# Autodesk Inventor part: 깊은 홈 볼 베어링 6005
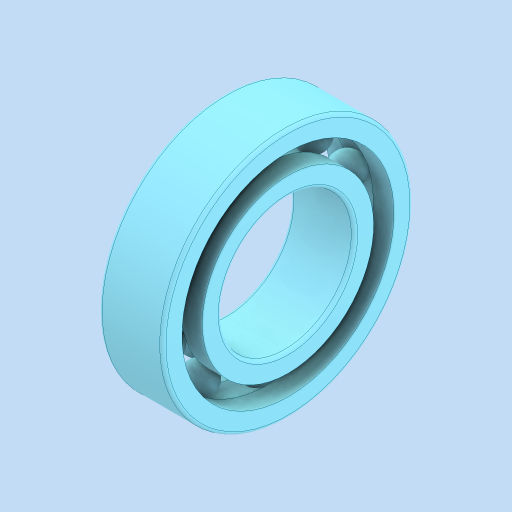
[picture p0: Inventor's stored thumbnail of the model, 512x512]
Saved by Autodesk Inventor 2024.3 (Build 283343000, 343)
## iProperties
Created: 2025-11
Part Number: 깊은 홈 볼 베어링 6005
Material: 강철, 연강
Description: 깊은 그루브 볼 베어링
Document SubType Name: Modeling
Designer: PC2-02
Density: 7.85 g/cm^3
Appearance: 기본값
Author: jhkim
Sending System: Autodesk Inventor 2026
Preprocessor: ST-DEVELOPER v20.1
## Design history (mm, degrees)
node "깊은 홈 볼 베어링 60051"
node "솔리드1"
node "솔리드2"
node "솔리드3"
node "솔리드4"
node "솔리드5"
node "솔리드6"
node "솔리드7"
node "솔리드8"
node "솔리드9"
node "솔리드10"
node "솔리드11"
node "솔리드12"
body "Solid1"
node "Solid1:1"
node "Solid1:2"
node "Solid1:3"
node "Solid1:4"
node "Solid1:5"
node "Solid1:6"
node "Solid1:7"
node "Solid1:8"
node "Solid1:9"
node "Solid1:10"
node "Solid1:11"
